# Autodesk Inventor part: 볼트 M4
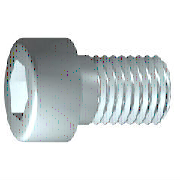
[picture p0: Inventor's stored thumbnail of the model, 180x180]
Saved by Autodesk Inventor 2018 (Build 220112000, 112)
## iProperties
IsCustomPart: 0
Created: 2012-02
Part Number: 볼트 M4
Material: 스테인리스강
Description: 6각 소켓 머리 캡 나사
Document SubType Name: Modeling
Standard: ISO 4762
Designer: mduedu
Standard Revision: Fourth edition 2004-03-01
Standards Organization: ISO
Language: ko-KR
Size Designation: M4 x 12
Categories: <MemberInstance><Categories><Category DisplayName="조임쇠" InternalName="e4da775c-781d-43d5-af7c-5136215cf5a6" Mnemonic="FSTN"><Category DisplayName="볼트" InternalN
Density: 8.08 g/cm^3
Appearance: 반광택
Author: mduedu
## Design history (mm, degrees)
sketch "스케치1"
  geometry: L1 (-1, 0)-(12, 0); L2 (12, 0)-(12, 2); L3 (12, 2)-(1.75, 2); L4 (1.75, 2)-(1.32, 2); L5 (1.32, 2)-(0, 2); L6 (0, 2)-(0, 3.5); L7 (0, 3.5)-(-4, 3.5); L8 (-4, 3.5)-(-4, 1.732); L9 (-4, 1.732)-(-2, 1.732); L10 (-2, 1.732)-(-1, 0); L11 (-7.2, 0)-(15.2, 0) reference; L12 (0, -0.7)-(0, 4.2) reference; L13 (1.75, 2)-(0, 2)
  constraints: 22 end point, 6 parallel, 2 collinear, 2 perpendicular, 1 horizontal, 1 point on line
  dimensions: "d1" = 10.25 distance from line of L3.end L2 (= GEL); "d2" = 0.42952 distance of L4.end L3.end (computed from GAL); "d3" = 4 distance between parallel lines of L8 L6 (= KOH); "d4" = 2 distance of L8.end L9.end (= INTI); "d5" = 60 deg angle of L10 L1; "d6" = 4 diameter of L3 L1 (= GD); "d7" = 4 diameter of L5 L1 (= BDM); "d8" = 3.4641 diameter of L9 L1 (= 1.1547 x SW); "d9" = 7 diameter of L7 L1 (= KOD); "d26" = 12 distance between parallel lines of L12 L2 (= NLG)
revolve "본체" sketch "스케치1" stored, may be unused: angle "d10" = 90 deg
sketch "스케치2"
  geometry: L1 (0, -4.9)-(0, 4.9) reference; L2 (-4.9, 0)-(4.9, 0) reference; L3 (1.732, 0)-(0.866, -1.5); L4 (0.866, -1.5)-(-0.866, -1.5); L5 (-0.866, -1.5)-(-1.732, 0); L6 (-1.732, 0)-(-0.866, 1.5); L7 (-0.866, 1.5)-(0.866, 1.5); L8 (0.866, 1.5)-(1.732, 0); 2 further points
  constraints: 12 end point, 1 coincident, 1 horizontal alignment, 1 point on line, 12 other
extrude "슬롯" join sketch "스케치2" stored distance "d11" = 10; taper "d12" = 0 deg
workplane "Work Plane1"
fillet "Fillet2" dims "d30" = 0.1 (= R)
body "Solid1"
fillet "모깎기1" dims "d17" = 0.4 (= RR)
feature "스레드" dims "d13" = 10.25 (= GEL), "d14" = 0
chamfer "모따기1" distance "d15" = 0.42941 (= -0.5 x SPD + 0.5 x GD); stored, may be unused: second distance "d16" = 0.42941 (= GUL), angle "d27" = 45 deg
other parameters: "GD" = 4 [user parameter; used in 2 equation terms], "NLG" = 12 [user parameter; used in 1 equation term], "GEL" = 10.25 [user parameter; used in 2 equation terms], "KOD" = 7 [user parameter; used in 1 equation term], "KOH" = 4 [user parameter; used in 1 equation term], "INTI" = 2 [user parameter; used in 1 equation term], "GAL" = 0.42941 (= 0.61345 x PTC) [user parameter; used in 1 equation term], "GUL" = 0.42941 (= 0.61345 x PTC) [user parameter; used in 1 equation term], "BDM" = 4 (= NND) [user parameter; used in 1 equation term], "SW" = 3 [user parameter; used in 2 equation terms], "RR" = 0.4 [user parameter; used in 1 equation term], "SPD" = 3.14117 (= NND - 1.2269 x PTC) [user parameter; used in 1 equation term], "d19" = 0, "d28" = 0, "d29" = 0, "R" = 0.1 [user parameter; used in 1 equation term], "TOA" = 30 deg [user parameter], "GD1" = 3.14117 (= THREADDIA - 1.2269 x PTC) [user parameter], "THREADDIA" = 4 [user parameter; used in 1 equation term], "FAWI" = 45 deg [user parameter], "TPU" = 14.28571 (computed from PTC) [user parameter], "PTC" = 0.7 [user parameter; used in 5 equation terms], "NND" = 4 [user parameter; used in 2 equation terms], "E0" = 3.465 (= 1.155 x SW) [user parameter]
